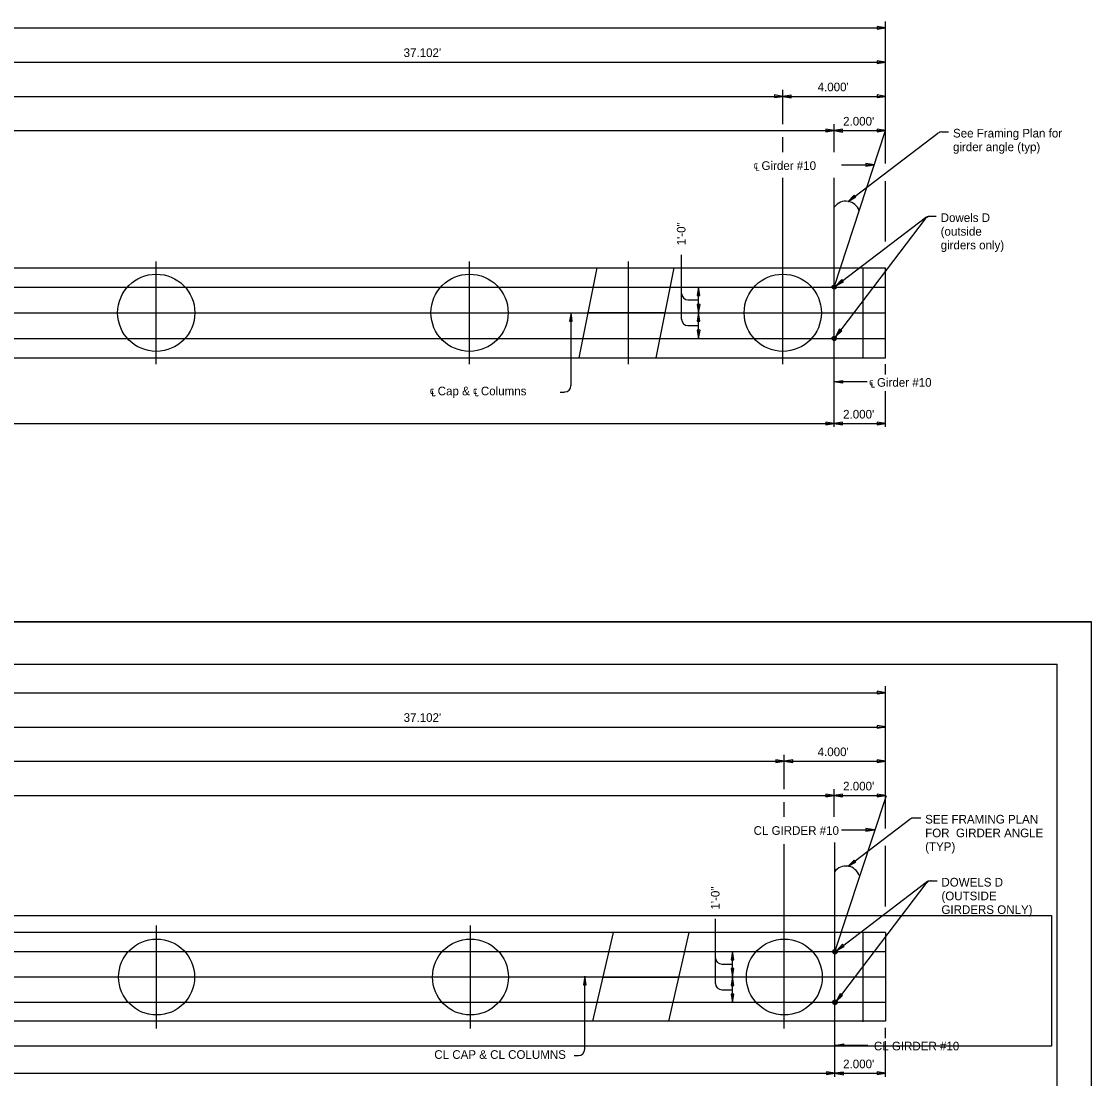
# Model space of a CAD drawing. Extents: x 983 to 1084, y 977 to 1031.
# Drawn here: x 1018.39 to 1034, y 1015.34 to 1030.76 of the extents above; entities that cross this region are included whole.
import ezdxf

# ---------------------------------------------------------------- set-up
doc = ezdxf.new("R2010")
doc.units = 0
for name, color, linetype in [('Bent', 7, 'Continuous'), ('BORD_lines_major', 7, 'Continuous'), ('D_BATCH_PLOT', 7, 'Continuous'), ('D_SHEET', 7, 'Continuous'), ('D_SHEET_TXT_DATAFIELD', 7, 'Continuous'), ('DILLED SHAFTS', 7, 'Continuous'), ('Working Level 1', 7, 'Continuous')]:
    doc.layers.add(name, color=color, linetype=linetype)

msp = doc.modelspace()

# ---------------------------------------------------------------- linework, layer by layer
at = {"layer": 'Bent'}
for p, q in [((1030.995, 1017.465), (1005.143, 1017.464)), ((1027.018, 1017.465), (1026.719, 1016.171)), ((1028.126, 1017.465), (1027.827, 1016.171)), ((1030.995, 1017.465), (1030.995, 1016.171)), ((1026.868, 1016.817), (1027.977, 1016.817)), ((1030.995, 1016.171), (1005.143, 1016.171))]:
    msp.add_line(p, q, dxfattribs=at)
at = {"layer": 'BORD_lines_major'}
for p in [(1002.413, 1021.382), (1033.5, 1000.5)]:
    msp.add_line(p, (1033.5, 1021.382), dxfattribs=at)
at = {"layer": 'D_BATCH_PLOT'}
msp.add_lwpolyline([(1000, 1000), (1034, 1000), (1034, 1022), (1000, 1022)], close=True, dxfattribs=at)
at = {"layer": 'D_SHEET'}
for p in [(1000, 1022), (1034, 1000)]:
    msp.add_line(p, (1034, 1022), dxfattribs=at)
at = {"layer": 'D_SHEET_TXT_DATAFIELD'}
msp.add_lwpolyline([(1002.738, 1017.713), (1033.414, 1017.713), (1033.414, 1015.809), (1002.738, 1015.809)], close=True, dxfattribs=at)
at = {"layer": 'DILLED SHAFTS'}
for centre, radius in [((1020.359, 1016.817), 0.554), ((1024.938, 1016.817), 0.554), ((1029.517, 1016.817), 0.554), ((1030.256, 1017.187), 0.0339), ((1030.256, 1017.187), 0.0271), ((1030.256, 1017.187), 0.0203), ((1030.256, 1017.187), 0.0136), ((1030.256, 1017.187), 0.00678), ((1030.256, 1016.448), 0.0339), ((1030.256, 1016.448), 0.0271), ((1030.256, 1016.448), 0.0203), ((1030.256, 1016.448), 0.0136), ((1030.256, 1016.448), 0.00678)]:
    msp.add_circle(centre, radius, dxfattribs=at)
at = {"layer": 'Working Level 1'}
for p, q in [((1005.143, 1030.664), (1030.997, 1030.664)), ((1030.995, 1028.851), (1030.995, 1030.757)), ((1030.995, 1028.683), (1030.995, 1030.757)), ((1005.143, 1030.164), (1030.995, 1030.164)), ((1029.495, 1029.257), (1029.495, 1029.757)), ((1003.232, 1029.664), (1030.995, 1029.664)), ((1030.245, 1028.851), (1030.245, 1029.257)), ((1003.232, 1029.164), (1030.995, 1029.164)), ((1029.495, 1028.851), (1029.495, 1029.07)), ((1030.245, 1026.882), (1030.995, 1029.164)), ((1030.449, 1028.132), (1031.756, 1029.126)), ((1031.813, 1029.145), (1031.914, 1029.145)), ((1030.351, 1028.664), (1030.831, 1028.664)), ((1029.495, 1025.757), (1029.495, 1028.476)), ((1030.245, 1025.758), (1030.245, 1028.477)), ((1030.995, 1027.547), (1030.995, 1028.428)), ((1031.573, 1027.877), (1030.264, 1026.157)), ((1030.27, 1026.901), (1031.576, 1027.895)), ((1031.633, 1027.914), (1031.734, 1027.914)), ((1028.017, 1026.414), (1028.017, 1027.353)), ((1020.354, 1025.757), (1020.354, 1027.257)), ((1024.925, 1025.757), (1024.925, 1027.257)), ((1027.245, 1025.757), (1027.245, 1027.257)), ((1005.143, 1027.164), (1030.995, 1027.164)), ((1026.781, 1027.164), (1026.517, 1025.851)), ((1027.906, 1027.164), (1027.642, 1025.851)), ((1030.667, 1025.851), (1030.667, 1027.164)), ((1030.995, 1025.851), (1030.995, 1027.164)), ((1005.143, 1026.882), (1030.995, 1026.882)), ((1028.267, 1026.132), (1028.267, 1026.882)), ((1028.111, 1026.695), (1028.267, 1026.695)), ((1004.237, 1026.507), (1030.995, 1026.507)), ((1026.405, 1025.445), (1026.405, 1026.507)), ((1027.774, 1026.507), (1026.649, 1026.507)), ((1028.111, 1026.32), (1028.267, 1026.32)), ((1005.143, 1026.132), (1030.995, 1026.132)), ((1005.143, 1025.851), (1030.995, 1025.851)), ((1030.245, 1024.841), (1030.245, 1025.757)), ((1030.995, 1025.608), (1030.995, 1025.757)), ((1030.725, 1025.501), (1030.245, 1025.501)), ((1026.249, 1025.351), (1026.311, 1025.351)), ((1030.995, 1024.841), (1030.995, 1025.361)), ((1003.232, 1024.89), (1030.995, 1024.89)), ((1005.143, 1020.964), (1030.997, 1020.964)), ((1030.995, 1018.983), (1030.995, 1021.058)), ((1005.143, 1020.464), (1030.995, 1020.464)), ((1029.517, 1019.558), (1029.517, 1020.058)), ((1003.232, 1019.964), (1030.995, 1019.964)), ((1030.245, 1019.152), (1030.245, 1019.558)), ((1003.232, 1019.464), (1030.995, 1019.464)), ((1030.256, 1017.183), (1031.006, 1019.465)), ((1029.517, 1019.152), (1029.517, 1019.37)), ((1030.449, 1018.433), (1031.35, 1019.118)), ((1031.407, 1019.138), (1031.508, 1019.138)), ((1030.351, 1018.964), (1030.831, 1018.964)), ((1030.256, 1016.059), (1030.256, 1018.778)), ((1029.517, 1016.067), (1029.517, 1018.754)), ((1030.995, 1017.847), (1030.995, 1018.729)), ((1031.584, 1018.181), (1030.275, 1016.461)), ((1030.281, 1017.205), (1031.587, 1018.199)), ((1031.644, 1018.218), (1031.745, 1018.218)), ((1028.512, 1016.724), (1028.512, 1017.664)), ((1020.359, 1016.067), (1020.359, 1017.567)), ((1024.938, 1016.067), (1024.938, 1017.567)), ((1030.667, 1016.162), (1030.667, 1017.475)), ((1005.132, 1017.187), (1030.984, 1017.187)), ((1028.762, 1016.443), (1028.762, 1017.193)), ((1028.606, 1017.005), (1028.762, 1017.005)), ((1004.237, 1016.818), (1030.995, 1016.818)), ((1026.606, 1015.765), (1026.606, 1016.827)), ((1028.606, 1016.63), (1028.762, 1016.63)), ((1005.132, 1016.448), (1030.984, 1016.448)), ((1030.256, 1015.363), (1030.256, 1016.077)), ((1030.995, 1015.927), (1030.995, 1016.077)), ((1030.736, 1015.82), (1030.256, 1015.82)), ((1030.995, 1015.363), (1030.995, 1015.883)), ((1026.451, 1015.671), (1026.513, 1015.671)), ((1003.232, 1015.412), (1030.995, 1015.412))]:
    msp.add_line(p, q, dxfattribs=at)
for points in [[(1030.995, 1030.664), (1030.873, 1030.684), (1030.873, 1030.645)], [(1030.995, 1030.164), (1030.873, 1030.184), (1030.873, 1030.145)], [(1029.495, 1029.664), (1029.373, 1029.684), (1029.373, 1029.645)], [(1029.495, 1029.664), (1029.618, 1029.644), (1029.618, 1029.682)], [(1030.995, 1029.664), (1030.873, 1029.684), (1030.873, 1029.645)], [(1030.245, 1029.164), (1030.123, 1029.184), (1030.123, 1029.145)], [(1030.245, 1029.164), (1030.368, 1029.144), (1030.368, 1029.183)], [(1030.995, 1029.164), (1030.873, 1029.184), (1030.873, 1029.145)], [(1030.831, 1028.664), (1030.708, 1028.684), (1030.708, 1028.645)], [(1030.449, 1028.132), (1030.559, 1028.191), (1030.536, 1028.221)], [(1028.267, 1026.882), (1028.247, 1026.76), (1028.286, 1026.76)], [(1030.27, 1026.901), (1030.379, 1026.959), (1030.356, 1026.99)], [(1028.267, 1026.507), (1028.287, 1026.63), (1028.248, 1026.63)], [(1026.405, 1026.507), (1026.385, 1026.385), (1026.423, 1026.385)], [(1028.267, 1026.507), (1028.247, 1026.385), (1028.286, 1026.385)], [(1028.267, 1026.132), (1028.287, 1026.255), (1028.248, 1026.255)], [(1030.264, 1026.157), (1030.354, 1026.242), (1030.323, 1026.266)], [(1030.245, 1025.501), (1030.368, 1025.521), (1030.368, 1025.482)], [(1030.245, 1024.89), (1030.123, 1024.91), (1030.123, 1024.872)], [(1030.245, 1024.89), (1030.368, 1024.87), (1030.368, 1024.909)], [(1030.995, 1024.89), (1030.873, 1024.91), (1030.873, 1024.872)], [(1030.995, 1020.965), (1030.873, 1020.985), (1030.873, 1020.946)], [(1030.995, 1020.465), (1030.873, 1020.485), (1030.873, 1020.446)], [(1029.517, 1019.965), (1029.395, 1019.985), (1029.395, 1019.946)], [(1029.517, 1019.965), (1029.64, 1019.945), (1029.64, 1019.983)], [(1030.995, 1019.965), (1030.873, 1019.985), (1030.873, 1019.946)], [(1030.245, 1019.465), (1030.123, 1019.485), (1030.123, 1019.446)], [(1030.245, 1019.465), (1030.368, 1019.445), (1030.368, 1019.483)], [(1030.995, 1019.465), (1030.873, 1019.485), (1030.873, 1019.446)], [(1030.831, 1018.964), (1030.708, 1018.984), (1030.708, 1018.945)], [(1030.449, 1018.433), (1030.559, 1018.492), (1030.536, 1018.522)], [(1030.281, 1017.205), (1030.39, 1017.264), (1030.367, 1017.294)], [(1028.762, 1017.193), (1028.742, 1017.07), (1028.781, 1017.07)], [(1028.762, 1016.818), (1028.782, 1016.94), (1028.744, 1016.94)], [(1026.606, 1016.827), (1026.586, 1016.705), (1026.625, 1016.705)], [(1028.762, 1016.818), (1028.742, 1016.695), (1028.781, 1016.695)], [(1030.275, 1016.461), (1030.365, 1016.547), (1030.334, 1016.57)], [(1028.762, 1016.443), (1028.782, 1016.565), (1028.744, 1016.565)], [(1030.256, 1015.82), (1030.379, 1015.84), (1030.379, 1015.802)], [(1030.256, 1015.412), (1030.134, 1015.432), (1030.134, 1015.394)], [(1030.256, 1015.412), (1030.379, 1015.392), (1030.379, 1015.431)], [(1030.995, 1015.412), (1030.873, 1015.432), (1030.873, 1015.394)]]:
    msp.add_lwpolyline(points, close=True, dxfattribs=at)
for centre, radius in [((1020.354, 1026.507), 0.563), ((1024.925, 1026.507), 0.563), ((1029.495, 1026.507), 0.563), ((1030.245, 1026.882), 0.0306), ((1030.245, 1026.882), 0.0245), ((1030.245, 1026.882), 0.0183), ((1030.245, 1026.882), 0.0122), ((1030.245, 1026.882), 0.00611), ((1030.245, 1026.132), 0.0306), ((1030.245, 1026.132), 0.0245), ((1030.245, 1026.132), 0.0183), ((1030.245, 1026.132), 0.0122), ((1030.245, 1026.132), 0.00611)]:
    msp.add_circle(centre, radius, dxfattribs=at)
for centre, radius, start, end in [((1031.813, 1029.051), 0.0938, 90, 127.2495), ((1030.415, 1027.929), 0.206, 18.6635, 143.8717), ((1031.648, 1027.82), 0.0938, 90, 142.7149), ((1031.633, 1027.82), 0.0938, 90, 127.2495), ((1028.111, 1026.789), 0.0938, 180, 270), ((1028.111, 1026.414), 0.0938, 180, 270), ((1026.311, 1025.445), 0.0938, 270, 0), ((1031.407, 1019.044), 0.0938, 90, 127.2495), ((1030.415, 1018.23), 0.206, 18.6635, 143.8717), ((1031.659, 1018.124), 0.0938, 90, 142.7149), ((1031.644, 1018.124), 0.0938, 90, 127.2495), ((1028.606, 1017.099), 0.0938, 180, 270), ((1028.606, 1016.724), 0.0938, 180, 270), ((1026.513, 1015.765), 0.0938, 270, 0)]:
    msp.add_arc(centre, radius, start, end, dxfattribs=at)

# ---------------------------------------------------------------- texts
for s, p in [("37.102'", (1023.963, 1030.238)), ("4.000'", (1030.003, 1029.738)), ("2.000'", (1030.375, 1029.238)), ('See Framing Plan for ', (1031.978, 1029.064)), ('girder angle (typ)', (1031.978, 1028.864)), ('℄ Girder #10', (1029.069, 1028.591)), ('Dowels D', (1031.798, 1027.832)), ('(outside', (1031.798, 1027.632)), ('girders only)', (1031.798, 1027.432)), ('℄ Girder #10', (1030.754, 1025.428)), ('℄ Cap & ℄ Columns', (1024.345, 1025.303)), ("2.000'", (1030.375, 1024.964)), ("37.102'", (1023.963, 1020.539)), ("4.000'", (1030.003, 1020.039)), ("2.000'", (1030.375, 1019.539)), ('SEE FRAMING PLAN', (1031.572, 1019.056)), ('CL GIRDER #10', (1029.069, 1018.891)), ('FOR  GIRDER ANGLE', (1031.572, 1018.856)), ('(TYP)', (1031.572, 1018.656)), ('DOWELS D', (1031.809, 1018.137)), ('(OUTSIDE', (1031.809, 1017.937)), ('GIRDERS ONLY)', (1031.809, 1017.737)), ('CL GIRDER #10', (1030.824, 1015.747)), ('CL CAP & CL COLUMNS', (1024.411, 1015.623)), ("2.000'", (1030.375, 1015.486))]:
    msp.add_text(s, height=0.126, dxfattribs=at).set_placement(p)
for p in [(1028.076, 1027.491), (1028.572, 1017.801)]:
    msp.add_text('1\'-0"', height=0.126, rotation=90, dxfattribs=at).set_placement(p)

doc.saveas('drawing.dxf')
